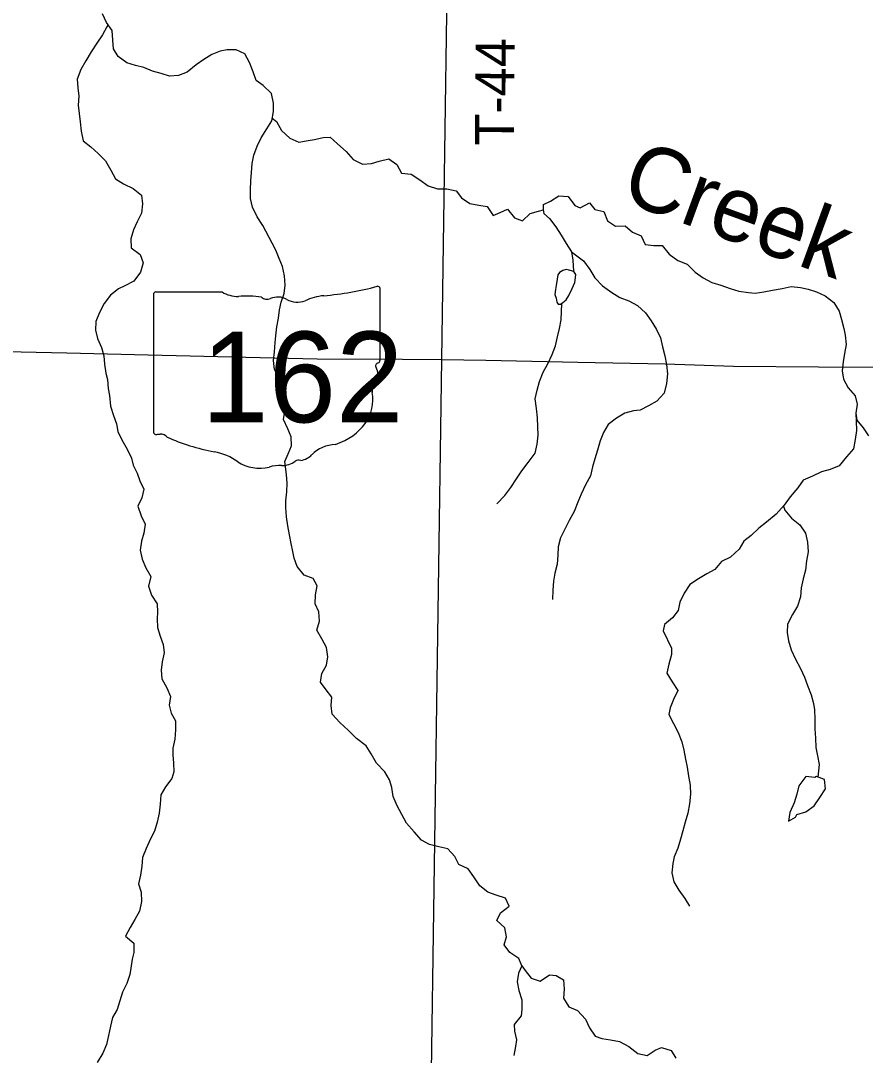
# Model space of a CAD drawing. Extents: x 1857828 to 2277390, y 930619 to 1324581.
# Drawn here: x 2047753 to 2054244, y 1124206 to 1132150 of the extents above; entities that cross this region are included whole.
import ezdxf

# ---------------------------------------------------------------- set-up
doc = ezdxf.new("R2010")
doc.units = 0
for name, color, linetype in [('GM_X_Major_River', 7, 'Continuous'), ('GM_X_Minor_Lake', 7, 'Continuous'), ('GM_X_Minor_River', 7, 'Continuous'), ('GM_X_Minor_River_Text', 7, 'Continuous'), ('GM_X_State_Location', 7, 'Continuous'), ('GM_X_State_Route', 7, 'Continuous'), ('GM_X_State_Shield', 7, 'Continuous'), ('GM_X_Township_Road', 7, 'Continuous'), ('GM_X_Township_Road_Text', 7, 'Continuous')]:
    doc.layers.add(name, color=color, linetype=linetype)

msp = doc.modelspace()

# ---------------------------------------------------------------- linework, layer by layer
at = {"layer": 'GM_X_Major_River'}
for points in [[(2049570.5, 1131185.4), (2049600.1, 1131249.9), (2049645.8, 1131318.5), (2049683.4, 1131381), (2049695, 1131453.4), (2049696.5, 1131517.7), (2049681.8, 1131591.9), (2049617.1, 1131651.8), (2049562.6, 1131689.6), (2049540, 1131757.7), (2049511.3, 1131827.8), (2049474.6, 1131895.8), (2049410.1, 1131927.6), (2049339.8, 1131927.1), (2049285.7, 1131916.6), (2049221.6, 1131890.1), (2049161.6, 1131851.5), (2049101.7, 1131810.9), (2049031.8, 1131754.2), (2048965.7, 1131729.6), (2048897.5, 1131725.2), (2048833, 1131744.8), (2048766.6, 1131762.4), (2048700.1, 1131790.1), (2048635.7, 1131805.7), (2048569.3, 1131825.3), (2048502.6, 1131875.1), (2048466, 1131935.1), (2048461.5, 1132001.4), (2048456.9, 1132073.7), (2048412.3, 1132135.6), (2048381.6, 1132203.7)], [(2051604, 1124892.9), (2051580.8, 1124948), (2051512.1, 1124995.7), (2051467.5, 1125053.7), (2051487.1, 1125116.1), (2051472.5, 1125184.2), (2051411.8, 1125240.1), (2051441.5, 1125300.5), (2051507.4, 1125351.2), (2051478.8, 1125413.3), (2051408.3, 1125434.9), (2051343.9, 1125458.6), (2051281.2, 1125506.3), (2051234.5, 1125576.3), (2051191.8, 1125638.3), (2051119.3, 1125669.9), (2051088.7, 1125732), (2051036, 1125789.9), (2050967.6, 1125805.5), (2050895.2, 1125823.1), (2050834.6, 1125858.8), (2050777.9, 1125920.7), (2050719.1, 1125988.6), (2050645.8, 1126120.7), (2050615.1, 1126192.8), (2050604.6, 1126261), (2050588, 1126321.1), (2050551.4, 1126383.1), (2050488.6, 1126449), (2050445.9, 1126521), (2050407.3, 1126581), (2050334.5, 1126638.8), (2050271.8, 1126700.6), (2050207, 1126760.4), (2050146.3, 1126824.3), (2050139.7, 1126892.5), (2050143.3, 1126956.8), (2050100.7, 1127012.8), (2050056, 1127070.7), (2050067.6, 1127137.1), (2050103.2, 1127201.6), (2050112.8, 1127266), (2050102.2, 1127338.2), (2050067.5, 1127404.3), (2050028.9, 1127470.3), (2050048.4, 1127538.7), (2050043.8, 1127611), (2050017.3, 1127673.1), (2050018.7, 1127741.4), (2050032.3, 1127809.8), (2049999.7, 1127867.8), (2049931.2, 1127893.5), (2049878.5, 1127959.4), (2049853.9, 1128023.5), (2049843.4, 1128073.7), (2049830.9, 1128135.8), (2049818.3, 1128202), (2049805.8, 1128272.3), (2049797.2, 1128340.5), (2049790.6, 1128412.8), (2049790.2, 1128463), (2049797.7, 1128531.3), (2049801.3, 1128597.7), (2049796.7, 1128665.9), (2049783.9, 1128766.3), (2049809.5, 1128824.7), (2049833.2, 1128885.1), (2049830.7, 1128953.4), (2049806.1, 1129015.5), (2049773.4, 1129087.6), (2049782.9, 1129152), (2049796.5, 1129216.3), (2049792, 1129282.6), (2049773.4, 1129344.7), (2049736.8, 1129406.8), (2049704.1, 1129472.8), (2049695.6, 1129541.1), (2049703.1, 1129607.4), (2049708.6, 1129679.8), (2049714.2, 1129730), (2049721.7, 1129798.4), (2049733.3, 1129866.7), (2049742.8, 1129929.1), (2049754.4, 1129989.4), (2049778, 1130055.9), (2049785.6, 1130118.2), (2049781, 1130190.5), (2049764.4, 1130262.7), (2049739.8, 1130324.8), (2049713.2, 1130386.9), (2049686.7, 1130440.9), (2049613.3, 1130577), (2049570.6, 1130645), (2049533.9, 1130717.1), (2049519.3, 1130785.3), (2049518.8, 1130851.6), (2049522.3, 1130919.9), (2049525.8, 1130984.2), (2049533.3, 1131052.6), (2049544.9, 1131116.9), (2049570.5, 1131185.4)]]:
    msp.add_lwpolyline(points, dxfattribs=at)
at = {"layer": 'GM_X_Minor_Lake'}
for points in [[(2051967.5, 1130235), (2051944.4, 1130240.6), (2051920.5, 1130232.2), (2051894.6, 1130215.7), (2051880.8, 1130197.4), (2051875.3, 1130165.2), (2051868, 1130116.9), (2051862.4, 1130086.7), (2051859.1, 1130046.4), (2051867.5, 1130018.4), (2051874, 1129988.4), (2051884.3, 1129972.5), (2051902.4, 1129972.7), (2051920.3, 1129985.1)], [(2051917.5, 1129981.9), (2051946.1, 1130005.5), (2051965.7, 1130039.9), (2051991, 1130092.6), (2052010.4, 1130139.1), (2052017.8, 1130177.3), (2052019.5, 1130201.5), (2052005, 1130225.4), (2051966.7, 1130234.8)], [(2051920.3, 1129985.1), (2051946.1, 1130005.5), (2051965.7, 1130039.9), (2051991, 1130092.6), (2052010.4, 1130139.1), (2052017.8, 1130177.3), (2052019.5, 1130201.5), (2052005, 1130225.4), (2051967.5, 1130235)], [(2053868.3, 1126345.5), (2053855.9, 1126339.5), (2053787.6, 1126347.1), (2053733.9, 1126274.4), (2053718.3, 1126210), (2053696.7, 1126143.6), (2053665.1, 1126071), (2053653.6, 1126004.7), (2053707.6, 1126035.2)], [(2053868.3, 1126345.5), (2053855.9, 1126339.5), (2053787.6, 1126347.1), (2053733.9, 1126274.4), (2053718.3, 1126210), (2053696.7, 1126143.6), (2053665.1, 1126071), (2053653.6, 1126004.7), (2053707.6, 1126035.2)], [(2053707.6, 1126035.2), (2053717.5, 1126055.3), (2053787.6, 1126073.9), (2053851.6, 1126120.5), (2053895.3, 1126185.1), (2053936.9, 1126251.7), (2053930.3, 1126323.9), (2053867.9, 1126345.6)], [(2053707.6, 1126035.2), (2053717.5, 1126055.3), (2053787.6, 1126073.9), (2053851.6, 1126120.5), (2053895.3, 1126185.1), (2053936.9, 1126251.7), (2053930.3, 1126323.9), (2053868.3, 1126345.5)]]:
    msp.add_lwpolyline(points, dxfattribs=at)
at = {"layer": 'GM_X_Minor_River'}
for points in [[(2048424.8, 1132117.1), (2048416.5, 1132103.5), (2048382.9, 1132041), (2048337.2, 1131976.4), (2048295.5, 1131909.8), (2048253.8, 1131841.3), (2048216.2, 1131774.7), (2048186.6, 1131702.2), (2048193.2, 1131633.9), (2048199.7, 1131569.7), (2048196.2, 1131501.4), (2048202.7, 1131437.1), (2048211.2, 1131372.9), (2048217.8, 1131300.7), (2048232.4, 1131228.4), (2048293.1, 1131180.6), (2048349.7, 1131130.8), (2048404.3, 1131074.9), (2048447.1, 1131002.9), (2048481.7, 1130934.8), (2048544.3, 1130897.1), (2048616.9, 1130861.5), (2048681.6, 1130809.7), (2048690.1, 1130743.4), (2048680.6, 1130673.1), (2048649, 1130606.6), (2048619.3, 1130544.1), (2048599.8, 1130475.6), (2048602.3, 1130405.4), (2048671, 1130355.6), (2048693.6, 1130291.5), (2048674, 1130219), (2048622.3, 1130150.4), (2048554.3, 1130113.8), (2048504.3, 1130091.3), (2048442.4, 1130042.7), (2048394.7, 1129978.1), (2048359.1, 1129909.5), (2048331.5, 1129841), (2048328, 1129772.7), (2048344.5, 1129708.6), (2048373.2, 1129640.4), (2048391.8, 1129576.3), (2048396.3, 1129512), (2048406.8, 1129443.8), (2048421.3, 1129393.7), (2048425.8, 1129325.4), (2048436.3, 1129273.3), (2048442.9, 1129191), (2048467.6, 1129118.8), (2048490.2, 1129054.7), (2048500.7, 1128994.5), (2048531.3, 1128930.4), (2048572, 1128860.4), (2048604.7, 1128790.3), (2048617.1, 1128736.2), (2048647.7, 1128676.1), (2048668.3, 1128616), (2048698.9, 1128551.9), (2048685.3, 1128487.5), (2048653.7, 1128421), (2048678.4, 1128348.9), (2048709, 1128284.8), (2048699.5, 1128214.4), (2048681.9, 1128154.1), (2048670.4, 1128083.7), (2048687, 1128015.5), (2048715.6, 1127949.4), (2048752.3, 1127881.3), (2048734.8, 1127806.9), (2048757.4, 1127738.8), (2048802.1, 1127672.8), (2048804.6, 1127608.5), (2048800.9, 1127558.3), (2048803.5, 1127490), (2048826.1, 1127423.9), (2048848.7, 1127359.7), (2048855.2, 1127295.5), (2048841.7, 1127227.1), (2048832.1, 1127162.8), (2048838.6, 1127096.5), (2048875.3, 1127028.5), (2048904, 1126960.4), (2048894.4, 1126894), (2048909, 1126831.8), (2048943.6, 1126773.8), (2048942.1, 1126703.5), (2048938.6, 1126633.2), (2048923.1, 1126562.8), (2048921.5, 1126512.6), (2048928, 1126448.3), (2048930.5, 1126382.1), (2048914.8, 1126331.7), (2048867.1, 1126267.1), (2048831.4, 1126206.6), (2048823.9, 1126134.2), (2048818.4, 1126065.9), (2048800.9, 1125995.5), (2048781.3, 1125927.1), (2048751.7, 1125866.6), (2048718.1, 1125794)], [(2049686.9, 1131401.5), (2049719.7, 1131375.2), (2049756.3, 1131307.2), (2049821.1, 1131247.4), (2049889.6, 1131217.7), (2049961.8, 1131230.3), (2050011.9, 1131238.6), (2050078.1, 1131253.2), (2050130.3, 1131255.5), (2050187, 1131203.7), (2050253.7, 1131145.9), (2050308.4, 1131084), (2050381, 1131048.3), (2050449.2, 1131052.8), (2050509.3, 1131071.3), (2050581.5, 1131089.9), (2050644.1, 1131046.1), (2050680.8, 1130978.1), (2050753.1, 1130972.6), (2050821.8, 1130928.8), (2050884.4, 1130883.1), (2050956.9, 1130859.4), (2051029.2, 1130857.9), (2051099.6, 1130844.3), (2051140.2, 1130790.4), (2051204.8, 1130746.6), (2051273.2, 1130733.1), (2051337.6, 1130723.4), (2051384.3, 1130653.5), (2051438.3, 1130677.9), (2051494.4, 1130702.4), (2051549.1, 1130636.5), (2051609.6, 1130612.8), (2051667.4, 1130669.5), (2051731.5, 1130688)], [(2051731.5, 1130688), (2051771.3, 1130696.5), (2051771.3, 1130739.5), (2051825.3, 1130764.9), (2051888.5, 1130805.6), (2051959.4, 1130799.8), (2052012.4, 1130732.1), (2052053.4, 1130713.9), (2052124.2, 1130752.2), (2052165.3, 1130701), (2052235.7, 1130685.4), (2052262.4, 1130613.3), (2052325, 1130571.5), (2052397.3, 1130574), (2052455.9, 1130526.2), (2052522.4, 1130498.5), (2052551, 1130432.4), (2052619.4, 1130422.9), (2052681.6, 1130423.3), (2052736.4, 1130357.4), (2052803, 1130307.6), (2052875.6, 1130280), (2052936.3, 1130220.1), (2052998.9, 1130176.4), (2053065.5, 1130138.7), (2053133.9, 1130119), (2053206.4, 1130093.4), (2053272.9, 1130073.8), (2053347.3, 1130062.2), (2053397.5, 1130058.6), (2053463.7, 1130069.1), (2053531.9, 1130081.6), (2053604.1, 1130094.1), (2053674.3, 1130108.7), (2053744.7, 1130101.1), (2053805, 1130087.5), (2053869.5, 1130067.8), (2053936, 1130036.1), (2054002.7, 1129986.4), (2054043.4, 1129920.3), (2054059.9, 1129856.2), (2054078.5, 1129786), (2054089, 1129735.8), (2054095.5, 1129663.6), (2054084, 1129595.2), (2054074.5, 1129530.9), (2054067, 1129462.5), (2054075.5, 1129396.3), (2054112.2, 1129330.2), (2054166.9, 1129270.3), (2054181.4, 1129206.2), (2054171.9, 1129135.8)], [(2051731.5, 1130688), (2051732.6, 1130686.7)], [(2051769, 1130698.8), (2051773.6, 1130669.8), (2051816.3, 1130632.3), (2051865, 1130566.3), (2051905.7, 1130502.3), (2051946.3, 1130440.3), (2051985, 1130374.3), (2051997.5, 1130312.1), (2052001.1, 1130225.7)], [(2052010.2, 1130355.8), (2051984.9, 1130374.9), (2052077.9, 1130306.7), (2052126.6, 1130240.7), (2052165.3, 1130174.7), (2052224, 1130114.8), (2052296.7, 1130063.1), (2052357.3, 1130025.3), (2052427.8, 1129999.7), (2052494.4, 1129962), (2052555, 1129906.2), (2052597.7, 1129844.2), (2052640.4, 1129778.2), (2052669, 1129714.1), (2052685.6, 1129645.9), (2052702.2, 1129575.7), (2052716.8, 1129509.5), (2052723.4, 1129437.3), (2052715.9, 1129362.9), (2052698.4, 1129290.4), (2052642.6, 1129227.8), (2052578.6, 1129193.2), (2052512.6, 1129158.6), (2052462.4, 1129154.3), (2052396.2, 1129135.7), (2052332.3, 1129097.1), (2052268.4, 1129048.5), (2052230.7, 1128987.9), (2052207.1, 1128923.5), (2052185.5, 1128853.1), (2052165.9, 1128786.6), (2052146.3, 1128724.2), (2052130.8, 1128655.8), (2052093.2, 1128585.3), (2052059.6, 1128514.7), (2052033.9, 1128452.3), (2052006.3, 1128381.8), (2051968.7, 1128313.2), (2051935.1, 1128244.7), (2051901.5, 1128178.2), (2051883.9, 1128109.8), (2051880.4, 1128045.4), (2051876.9, 1127977.1), (2051857.3, 1127906.7), (2051847.8, 1127846.4), (2051842.3, 1127778), (2051840.8, 1127705.7)], [(2051413.4, 1128440), (2051473.1, 1128504.7), (2051520.9, 1128565.3), (2051564.5, 1128631.8), (2051604.2, 1128694.4), (2051654, 1128757), (2051707.6, 1128829.7), (2051723.2, 1128898.1), (2051730.7, 1128968.4), (2051726.2, 1129030.7), (2051723.6, 1129101), (2051717.1, 1129173.2), (2051706.4, 1129245.5), (2051722, 1129313.9), (2051739.6, 1129380.3), (2051769.1, 1129450.8), (2051804.8, 1129515.3), (2051836.4, 1129587.9), (2051864, 1129654.4), (2051879.5, 1129722.8), (2051895.1, 1129787.1), (2051906.7, 1129853.5), (2051912.9, 1129979.6)], [(2054171.9, 1129135.8), (2054172.4, 1129075.5), (2054174.9, 1129003.2), (2054165.4, 1128934.9), (2054153.9, 1128862.5), (2054100.2, 1128799.8), (2054042.4, 1128731.1), (2053974.3, 1128704.6), (2053908.2, 1128686), (2053838.1, 1128653.4), (2053766.1, 1128622.8), (2053724.4, 1128562.3), (2053666.6, 1128493.6), (2053620.9, 1128429), (2053559.2, 1128360.3), (2053485.3, 1128299.5), (2053425.4, 1128252.9), (2053365.6, 1128198.2), (2053309.7, 1128153.7), (2053274, 1128091.1), (2053208.2, 1128030.4), (2053138.1, 1127997.8), (2053086.4, 1127937.2), (2053026.4, 1127902.6), (2052962.4, 1127864), (2052896.5, 1127821.4), (2052850.8, 1127754.8), (2052819.2, 1127686.3), (2052805.6, 1127619.9), (2052761.8, 1127565.4), (2052700, 1127514.7), (2052690.3, 1127464.4), (2052755.6, 1127332.3), (2052754, 1127282.1), (2052734.4, 1127209.6), (2052718.9, 1127139.2), (2052759.6, 1127073.2), (2052802.3, 1127007.2), (2052770.7, 1126938.7), (2052743, 1126874.2), (2052733.4, 1126821.9), (2052770.1, 1126753.9), (2052804.8, 1126683.8), (2052833.4, 1126613.7), (2052848, 1126549.6), (2052862.6, 1126479.3), (2052875.1, 1126417.2), (2052885.7, 1126348.9), (2052898.2, 1126280.7), (2052900.8, 1126210.4), (2052893.3, 1126136.1), (2052879.8, 1126063.7), (2052860.3, 1125995.2), (2052842.7, 1125928.8), (2052823.1, 1125866.4), (2052803.5, 1125796), (2052775.9, 1125729.5), (2052764.3, 1125679.2), (2052756.8, 1125606.8), (2052773.4, 1125538.7), (2052810, 1125472.6), (2052856.7, 1125410.7), (2052893.3, 1125350.7)], [(2054171.9, 1129135.8), (2054178.3, 1129083.6), (2054227, 1129023.7), (2054267.6, 1128961.7)], [(2053615.2, 1128422.6), (2053625.2, 1128390.8), (2053675.9, 1128330.9), (2053740.6, 1128279.1), (2053783.3, 1128215.1), (2053799.9, 1128145), (2053804.4, 1128072.7), (2053792.9, 1128002.3), (2053783.4, 1127929.9), (2053765.9, 1127863.5), (2053750.3, 1127795.1), (2053744.8, 1127726.8), (2053723.3, 1127654.3), (2053683.6, 1127589.8), (2053646, 1127517.2), (2053644.5, 1127452.9), (2053653, 1127388.7), (2053673.6, 1127318.5), (2053708.3, 1127246.4), (2053747, 1127176.4), (2053777.7, 1127110.3), (2053800.3, 1127046.2), (2053826.9, 1126974.1), (2053845.5, 1126907.9), (2053853.9, 1126857.7), (2053856.5, 1126785.4), (2053855, 1126713.1), (2053861.6, 1126640.8), (2053864.2, 1126568.6), (2053876.7, 1126504.4), (2053889.3, 1126438.2), (2053878.5, 1126342.2)], [(2048718.1, 1125794), (2048690.5, 1125725.6), (2048685, 1125657.2), (2048673.5, 1125588.8), (2048657.9, 1125522.4), (2048678.5, 1125458.3), (2048681.1, 1125386), (2048665.6, 1125313.6), (2048629.9, 1125247.1), (2048594.2, 1125186.6), (2048558.6, 1125120), (2048623.3, 1125066.2), (2048623.8, 1124995.9), (2048610.2, 1124943.6), (2048598.6, 1124875.2), (2048593, 1124825), (2048569.4, 1124756.5), (2048535.8, 1124690), (2048514.2, 1124623.6), (2048494.6, 1124557.1), (2048458.9, 1124494.6), (2048443.4, 1124430.2), (2048427.9, 1124357.8), (2048412.3, 1124287.4), (2048384.7, 1124220.9), (2048341.1, 1124150.3)], [(2051604.2, 1124892.9), (2051604.2, 1124893.5), (2051577.6, 1124837.5), (2051568.1, 1124769.1), (2051580.7, 1124702.9), (2051605.3, 1124630.8), (2051603.9, 1124558.4), (2051598.2, 1124508.2), (2051546.5, 1124441.6), (2051546.9, 1124391.3), (2051563.5, 1124325.2), (2051555.9, 1124272.9), (2051542.3, 1124204.5)], [(2051604, 1124893.1), (2051629.7, 1124855.9), (2051676.3, 1124798), (2051744.8, 1124774.3), (2051816.8, 1124823), (2051867, 1124819.4), (2051923.5, 1124785.6), (2051930.1, 1124713.3), (2051924.6, 1124645), (2051965.3, 1124577), (2052031.8, 1124549.3), (2052092.5, 1124483.5), (2052123.2, 1124417.4), (2052167.9, 1124351.4), (2052220.2, 1124335.7), (2052286.6, 1124324.1), (2052355, 1124312.5), (2052425.6, 1124272.8), (2052496.3, 1124219.1), (2052566.7, 1124203.5), (2052628.6, 1124246.1), (2052678.7, 1124266.5), (2052751.2, 1124242.9), (2052787.8, 1124182.9)]]:
    msp.add_lwpolyline(points, dxfattribs=at)
at = {"layer": 'GM_X_State_Route'}
msp.add_lwpolyline([(2045825.8, 1129648.4), (2046172.1, 1129638.3), (2046864.9, 1129625.8), (2047519.5, 1129613.2), (2048107.9, 1129600.5), (2048732.4, 1129583.8), (2049483.4, 1129567.4), (2050031.6, 1129554.6), (2050688.3, 1129552), (2050990.5, 1129548), (2051328.9, 1129543.4), (2052033.7, 1129528.9), (2052706.5, 1129516.4), (2053230.6, 1129497.4), (2053883.3, 1129492.9), (2054624.3, 1129488.5)], dxfattribs=at)
at = {"layer": 'GM_X_State_Shield'}
for p, q in [((2048774.4, 1130048.5), (2048774.4, 1128991.9)), ((2049301.2, 1130066.7), (2048791.5, 1130066.7)), ((2050514.6, 1129540.2), (2050514.6, 1130092.9)), ((2050514.4, 1129540.3), (2050514.6, 1129540.2))]:
    msp.add_line(p, q, dxfattribs=at)
for centre, major_axis, start_param, end_param in [((2048794.4, 1130050.8), (20.2, 0), 1.712693, 3.28349), ((2049422.5, 1130189.4), (195.5, 0), 4.042523, 4.731795), ((2049487.4, 1129473.5), (702, 0), 1.404758, 1.657858), ((2050130.1, 1129744), (371.3, 0), 1.699011, 2.107814), ((2049894.7, 1131507.3), (1845.5, 0), 4.814394, 5.042369), ((2050495.3, 1130095.2), (19.4, 0), 6.141152, 7.989035), ((2049646.7, 1130056.3), (56.4, 0), 3.836095, 5.185415), ((2049729.6, 1129934.1), (117.3, 0), 0.950623, 2.079405), ((2049880.9, 1130101.6), (141.1, 0), 4.081561, 5.145723), ((2050510.1, 1129499.6), (30, 0), 1.883978, 3.671073), ((2050319.4, 1129429.7), (180, 0), 5.934695, 6.695948), ((2050493.9, 1129538), (20.7, 0), 5.05454, 6.418171), ((2050584, 1129308.8), (130.9, 0), 2.387724, 3.262537), ((2049998.1, 1129238.5), (461.6, 0), 5.101752, 6.440018), ((2048794.5, 1128989.6), (20.3, 0), 3.00124, 4.508301), ((2048797.6, 1129097.7), (155.2, 0), 4.665946, 4.897461), ((2048829.4, 1128930.9), (56, 0), 0.519207, 1.627899), ((2049536, 1129880.3), (1332.7, 0), 4.195997, 4.488961), ((2050192.7, 1128695.3), (252.8, 0), 1.647645, 2.488434), ((2049138.6, 1128517.2), (417, 0), 0.823519, 1.323587), ((2049761.8, 1128846.6), (141, 0), 4.691044, 5.507374), ((2049889.4, 1128744.2), (39.7, 0), 1.147584, 2.315152), ((2049872.4, 1128889.5), (149.1, 0), 4.937069, 5.64225), ((2049589.6, 1128925.7), (264.6, 0), 4.026481, 4.996735), ((2049742.5, 1128560.4), (217.4, 0), 1.495662, 1.94098)]:
    msp.add_ellipse(centre, major_axis=major_axis, ratio=0.8, start_param=start_param, end_param=end_param, dxfattribs=at)
at = {"layer": 'GM_X_Township_Road'}
for points in [[(2050990.5, 1129548), (2051053.8, 1133973.1), (2051061.6, 1134730.4), (2051061.5, 1135106), (2051070.8, 1135250.6)], [(2050904.5, 1123729), (2050990.5, 1129548)]]:
    msp.add_lwpolyline(points, dxfattribs=at)

# ---------------------------------------------------------------- texts
at = {"layer": 'GM_X_Minor_River_Text'}
msp.add_text('Creek', height=500.26, rotation=339.92146, dxfattribs=at).set_placement((2052346.8, 1130774.8))
at = {"layer": 'GM_X_State_Location'}
for s in ['s', 'r']:
    msp.add_text(s, height=1, dxfattribs=at).set_placement((2049624.9, 1129450))
msp.add_text('162', height=1, rotation=0.00001, dxfattribs=at).set_placement((2049271.9, 1129377.2))
at = {"layer": 'GM_X_State_Shield'}
msp.add_text('162', height=696.1, dxfattribs=at).set_placement((2049141.3, 1129066.4))
at = {"layer": 'GM_X_Township_Road_Text'}
msp.add_text('T-44', height=300, rotation=89.64651, dxfattribs=at).set_placement((2051543.8, 1131189.7))

doc.saveas('drawing.dxf')
